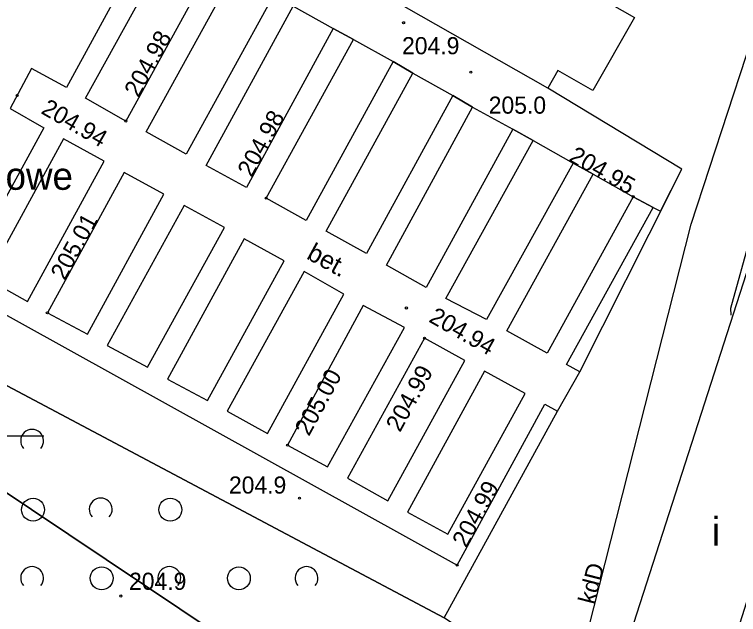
# Model space of a CAD drawing. Extents: x 6512400 to 6513200, y 6022500 to 6022750.
# Drawn here: x 6512751.21 to 6512782.87, y 6022592.19 to 6022618.44 of the extents above; entities that cross this region are included whole.
import ezdxf

# ---------------------------------------------------------------- set-up
doc = ezdxf.new("R2010")
doc.units = 0
for name, color, linetype in [('217-kontur klasyfikacyjny', 7, 'Continuous'), ('218-kontur użytku gruntowego', 7, 'Continuous'), ('219-działka ewidencyjna', 7, 'Continuous'), ('996-Tekst dodatkowy mały', 7, 'Continuous'), ('budynek', 7, 'Continuous'), ('chodnik', 7, 'Continuous'), ('chodnik (powierzchnia)', 7, 'Continuous'), ('inna budowla', 7, 'Continuous'), ('Komentarz lub etykieta na mapie', 7, 'Continuous'), ('ogrodzenie trwałe', 7, 'Continuous'), ('pikieta naturalna', 7, 'Continuous'), ('pikieta naturalna-Atr2', 7, 'Continuous'), ('pikieta sztuczna', 7, 'Continuous'), ('pikieta sztuczna-Atr2', 7, 'Continuous'), ('przewód elektroenergetyczny (linia)', 7, 'Continuous'), ('przewód kanalizacyjny (linia)', 7, 'Continuous'), ('przewód kanalizacyjny (linia)-Atr1', 7, 'Continuous'), ('punkt wysokościowy naturalny', 7, 'Continuous'), ('punkt wysokościowy naturalny-Atr2', 7, 'Continuous'), ('punkt wysokościowy sztuczny', 7, 'Continuous'), ('punkt wysokościowy sztuczny-Atr2', 7, 'Continuous'), ('Wstawianie ramki sekcyjnej z opisem', 7, 'Continuous'), ('zadrzewienie  zakrzewienie', 7, 'Continuous')]:
    doc.layers.add(name, color=color, linetype=linetype)

# ---------------------------------------------------------------- blocks, each defined once
blk = doc.blocks.new('PW02')
blk.add_circle((0, 0), 0.045)
blk = doc.blocks.new('PW01')
blk.add_circle((0, 0), 0.045)
blk = doc.blocks.new('RAMKA500K')
blk.add_line((347.5, 100), (352.5, 100))
blk = doc.blocks.new('OTZK1')
blk.add_circle((0, 0), 0.5)
blk = doc.blocks.new('OTZK2')
blk.add_arc((0, 0), 0.5, 318.85, 221.162)

msp = doc.modelspace()

# ---------------------------------------------------------------- linework, layer by layer
at = {"layer": '217-kontur klasyfikacyjny'}
for points in [[(6512735.75, 6022607.64), (6512773.05, 6022582.65)], [(6512773.05, 6022582.65), (6512735.75, 6022607.64)]]:
    msp.add_lwpolyline(points, dxfattribs=at)
at = {"layer": '218-kontur użytku gruntowego'}
for points in [[(6512735.75, 6022607.64), (6512773.05, 6022582.65)], [(6512773.05, 6022582.65), (6512735.75, 6022607.64)]]:
    msp.add_lwpolyline(points, dxfattribs=at)
at = {"layer": '219-działka ewidencyjna'}
msp.add_lwpolyline([(6512773.05, 6022582.65), (6512735.75, 6022607.64)], dxfattribs=at)
at = {"layer": 'budynek'}
msp.add_lwpolyline([(6512776.87, 6022587.41), (6512781.1, 6022585.98), (6512787.49, 6022606.19), (6512783.36, 6022607.54)], close=True, dxfattribs=at)
at = {"layer": 'chodnik'}
msp.add_lwpolyline([(6512763.4, 6022618.8), (6512765.15, 6022617.82), (6512766.04, 6022617.34), (6512767.77, 6022616.38), (6512768.63, 6022615.88), (6512770.38, 6022614.9), (6512771.24, 6022614.38), (6512773.01, 6022613.42), (6512773.89, 6022612.93), (6512775.64, 6022611.93), (6512776.52, 6022611.46), (6512778.27, 6022610.47), (6512779.14, 6022609.99), (6512779.47, 6022609.84), (6512780.39, 6022611.67), (6512774.54, 6022615.22), (6512760.59, 6022623.16)], dxfattribs=at)
at = {"layer": 'chodnik (powierzchnia)'}
for points in [[(6512757.29, 6022622.23), (6512753.49, 6022615.24), (6512751.96, 6022616.08), (6512751.03, 6022614.33), (6512752.5, 6022613.48), (6512749.14, 6022607.36)], [(6512757.29, 6022622.23), (6512758.16, 6022621.75), (6512759.91, 6022620.76), (6512760.79, 6022620.25), (6512762.54, 6022619.28), (6512763.4, 6022618.8), (6512765.15, 6022617.82), (6512766.04, 6022617.34), (6512767.77, 6022616.38), (6512768.63, 6022615.88), (6512770.38, 6022614.9), (6512771.24, 6022614.38), (6512773.01, 6022613.42), (6512773.89, 6022612.93), (6512775.64, 6022611.93), (6512776.52, 6022611.46), (6512778.27, 6022610.47), (6512779.14, 6022609.99)], [(6512759.91, 6022620.76), (6512756.08, 6022613.78), (6512754.32, 6022614.78), (6512758.16, 6022621.75)], [(6512762.54, 6022619.28), (6512758.72, 6022612.33), (6512756.97, 6022613.3), (6512760.79, 6022620.25)], [(6512747.15, 6022607.34), (6512770.57, 6022594.35), (6512774.41, 6022601.39), (6512774.96, 6022601.08), (6512775.93, 6022602.8), (6512775.35, 6022603.13), (6512779.14, 6022609.99), (6512778.27, 6022610.47), (6512774.5, 6022603.63), (6512772.74, 6022604.6), (6512776.52, 6022611.46), (6512775.64, 6022611.93), (6512771.86, 6022605.09), (6512770.07, 6022606.02), (6512773.89, 6022612.93), (6512773.01, 6022613.42), (6512769.21, 6022606.5), (6512767.48, 6022607.48), (6512771.24, 6022614.38), (6512770.38, 6022614.9), (6512766.6, 6022607.98), (6512764.85, 6022608.96), (6512768.63, 6022615.88), (6512767.77, 6022616.38), (6512763.97, 6022609.43), (6512762.22, 6022610.4), (6512766.04, 6022617.34), (6512765.15, 6022617.82), (6512761.36, 6022610.87), (6512759.59, 6022611.84), (6512763.4, 6022618.8)]]:
    msp.add_lwpolyline(points, dxfattribs=at)
for points in [[(6512753.36, 6022613), (6512750.01, 6022606.87), (6512751.78, 6022605.89), (6512755.14, 6022612.03)], [(6512756.01, 6022611.53), (6512752.65, 6022605.39), (6512754.4, 6022604.46), (6512757.75, 6022610.58)], [(6512758.63, 6022610.08), (6512755.27, 6022603.96), (6512757.03, 6022603.01), (6512760.39, 6022609.12)], [(6512761.26, 6022608.62), (6512757.9, 6022602.49), (6512759.65, 6022601.56), (6512763, 6022607.67)], [(6512763.88, 6022607.2), (6512760.52, 6022601.08), (6512762.28, 6022600.11), (6512765.62, 6022606.2)], [(6512766.46, 6022605.71), (6512763.15, 6022599.6), (6512764.9, 6022598.65), (6512768.27, 6022604.74)], [(6512769.14, 6022604.28), (6512765.78, 6022598.15), (6512767.54, 6022597.17), (6512770.9, 6022603.3)], [(6512771.77, 6022602.84), (6512768.4, 6022596.67), (6512770.17, 6022595.71), (6512773.54, 6022601.86)]]:
    msp.add_lwpolyline(points, close=True, dxfattribs=at)
at = {"layer": 'inna budowla'}
msp.add_lwpolyline([(6512760.59, 6022623.16), (6512763.64, 6022628.51), (6512768.2, 6022625.92), (6512767.41, 6022624.52), (6512778.32, 6022618.31), (6512776.51, 6022615.12), (6512774.98, 6022615.99), (6512774.54, 6022615.22)], close=True, dxfattribs=at)
at = {"layer": 'ogrodzenie trwałe'}
msp.add_lwpolyline([(6512744.3, 6022605.68), (6512748.08, 6022603.68), (6512764.51, 6022594.96), (6512770, 6022592.05), (6512774.96, 6022601.08), (6512775.93, 6022602.8), (6512779.97, 6022610.83), (6512780.39, 6022611.67), (6512774.54, 6022615.22)], dxfattribs=at)
at = {"layer": 'przewód elektroenergetyczny (linia)'}
msp.add_lwpolyline([(6512782.56, 6022605.29), (6512782.54, 6022605.59), (6512783.43, 6022608.8), (6512786.9, 6022619.73), (6512788.66, 6022625.18), (6512788.94, 6022625.46)], dxfattribs=at)
at = {"layer": 'przewód kanalizacyjny (linia)'}
msp.add_lwpolyline([(6512771.21, 6022579.63), (6512775.79, 6022589.49), (6512780.81, 6022609.27), (6512784.81, 6022621.53)], dxfattribs=at)
at = {"layer": 'zadrzewienie  zakrzewienie'}
msp.add_lwpolyline([(6512788.13, 6022581.61), (6512782.6, 6022584.18), (6512782.06, 6022584.86), (6512781.1, 6022585.98), (6512776.87, 6022587.41), (6512770, 6022592.05), (6512764.51, 6022594.96), (6512748.08, 6022603.68)], dxfattribs=at)

# ---------------------------------------------------------------- block references
at = {"layer": 'pikieta naturalna'}
for p in [(6512768.23, 6022618.08), (6512771.17, 6022615.92)]:
    msp.add_blockref('PW01', p, dxfattribs=at)
at = {"layer": 'pikieta sztuczna'}
for p in [(6512751.33, 6022614.9), (6512768.35, 6022605.6)]:
    msp.add_blockref('PW01', p, dxfattribs=at)
at = {"layer": 'punkt wysokościowy naturalny'}
for p in [(6512763.68, 6022597.28), (6512755.86, 6022593)]:
    msp.add_blockref('PW01', p, dxfattribs=at)
at = {"layer": 'punkt wysokościowy sztuczny'}
for p in [(6512756.08, 6022613.78), (6512762.22, 6022610.4), (6512778.27, 6022610.47), (6512752.65, 6022605.39), (6512769.14, 6022604.28), (6512763.15, 6022599.6), (6512770.57, 6022594.35)]:
    msp.add_blockref('PW02', p, dxfattribs=at)
at = {"layer": 'Wstawianie ramki sekcyjnej z opisem'}
msp.add_blockref('RAMKA500K', (6512400, 6022500), dxfattribs=at)
at = {"layer": 'zadrzewienie  zakrzewienie'}
for name, p in [('OTZK2', (6512751.984, 6022599.787)), ('OTZK2', (6512754.984, 6022596.787)), ('OTZK1', (6512752.026, 6022596.776)), ('OTZK1', (6512758.026, 6022596.776)), ('OTZK2', (6512751.984, 6022593.787)), ('OTZK1', (6512755.026, 6022593.776)), ('OTZK2', (6512757.984, 6022593.787)), ('OTZK1', (6512761.026, 6022593.776)), ('OTZK2', (6512763.984, 6022593.787))]:
    msp.add_blockref(name, p, dxfattribs=at)

# ---------------------------------------------------------------- texts
at = {"layer": '996-Tekst dodatkowy mały'}
msp.add_text(' bet.', height=0.8, rotation=331.366, dxfattribs=at).set_placement((6512763.68, 6022607.92))
msp.add_text('i', height=1.25, dxfattribs=at).set_placement((6512781.7, 6022595.2))
at = {"layer": 'Komentarz lub etykieta na mapie'}
msp.add_text('stanowisko plenerowe', height=1.2, dxfattribs=at).set_placement((6512737.98, 6022610.77))
at = {"layer": 'pikieta naturalna-Atr2'}
for s, p in [('204.9', (6512768.16, 6022616.7)), ('205.0', (6512771.95, 6022614.1))]:
    msp.add_text(s, height=0.75, dxfattribs=at).set_placement(p)
at = {"layer": 'pikieta sztuczna-Atr2'}
for rotation, p in [(329.962, (6512752.33, 6022614.14)), (330.376, (6512769.29, 6022605.02))]:
    msp.add_text('204.94', height=0.75, rotation=rotation, dxfattribs=at).set_placement(p)
at = {"layer": 'przewód kanalizacyjny (linia)-Atr1'}
msp.add_text('kdD', height=0.75, rotation=75.759, dxfattribs=at).set_placement((6512776.58, 6022592.6))
at = {"layer": 'punkt wysokościowy naturalny-Atr2'}
for p in [(6512760.59, 6022597.48), (6512756.22, 6022593.27)]:
    msp.add_text('204.9', height=0.75, dxfattribs=at).set_placement(p)
at = {"layer": 'punkt wysokościowy sztuczny-Atr2'}
for s, rotation, p in [('204.98', 61.246, (6512756.63, 6022614.77)), ('204.98', 61.395, (6512761.58, 6022611.28)), ('204.95', 330.255, (6512775.41, 6022612.06)), ('205.01', 61.311, (6512753.41, 6022606.77)), ('204.99', 61.272, (6512768.07, 6022600.13)), ('205.00', 61.554, (6512764.09, 6022599.96)), ('204.99', 61.39, (6512770.97, 6022595.07))]:
    msp.add_text(s, height=0.75, rotation=rotation, dxfattribs=at).set_placement(p)

doc.saveas('drawing.dxf')
